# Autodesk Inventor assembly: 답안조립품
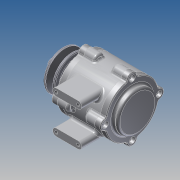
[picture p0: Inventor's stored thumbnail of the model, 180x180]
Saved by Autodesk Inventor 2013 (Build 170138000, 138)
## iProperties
Created: 2015-03
Part Number: 답안조립품
Document SubType Name: Assembly
Designer: kb543
Author: kb543
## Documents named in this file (10)
- C:\Users\kb543\Desktop\450305V1004\답안조립품.iam
- C:\Users\kb543\Desktop\450305V1004\본체.ipt
- C:\Users\kb543\Desktop\450305V1004\축.ipt
- C:\Users\kb543\Desktop\450305V1004\V벨트풀리.ipt
- C:\Users\kb543\Desktop\450305V1004\키(4 x 4 x 12).ipt
- C:\Users\kb543\Desktop\450305V1004\너트 M12x1.25.ipt
- C:\Users\kb543\Desktop\450305V1004\커버.ipt
- C:\Users\kb543\Desktop\450305V1004\커버2.ipt
- C:\Users\kb543\Desktop\450305V1004\베어링 6204.ipt
- C:\Users\kb543\Desktop\450305V1004\오일실.ipt
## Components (6 placed, 5 different names)
1. 그루브 풀리1:1 — 플러쉬:2
2. KS B 1311 (I) 4 x 4 x 12:1
3. KS B 1012 클래스 1 일반 - 미터 M12x1.25:1
4. KS B 2023 6204 - 20 x 47 x 14:1
5. KS B 2023 6204 - 20 x 47 x 14:2
6. KS B 2804 D D - 20 32 8:1
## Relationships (1: Flush 1)
- 플러쉬:2 [Flush]: 그루브 풀리1:1
